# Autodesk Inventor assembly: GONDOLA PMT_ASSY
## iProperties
Shininess: 64.0
Length Units: 11272
Angle Units: 11279
Time Units: 11290
Mass Units: 11286
Length Display Precision: 3
Angle Display Precision: 2
Compacted: True
Part Number: GONDOLA PMT_ASSY
Document SubType Name: Assembly
Created: 2004-08
Designer: John Blackburn
Manufacturer: Standard
Standards Organization: Custom
Density: 0.0
Volumn: 0.0
Area: 0.0
PropertySet Name: Model Information
Control State: 0
Master: False
Checked Out: False
Author: John Blackburn
